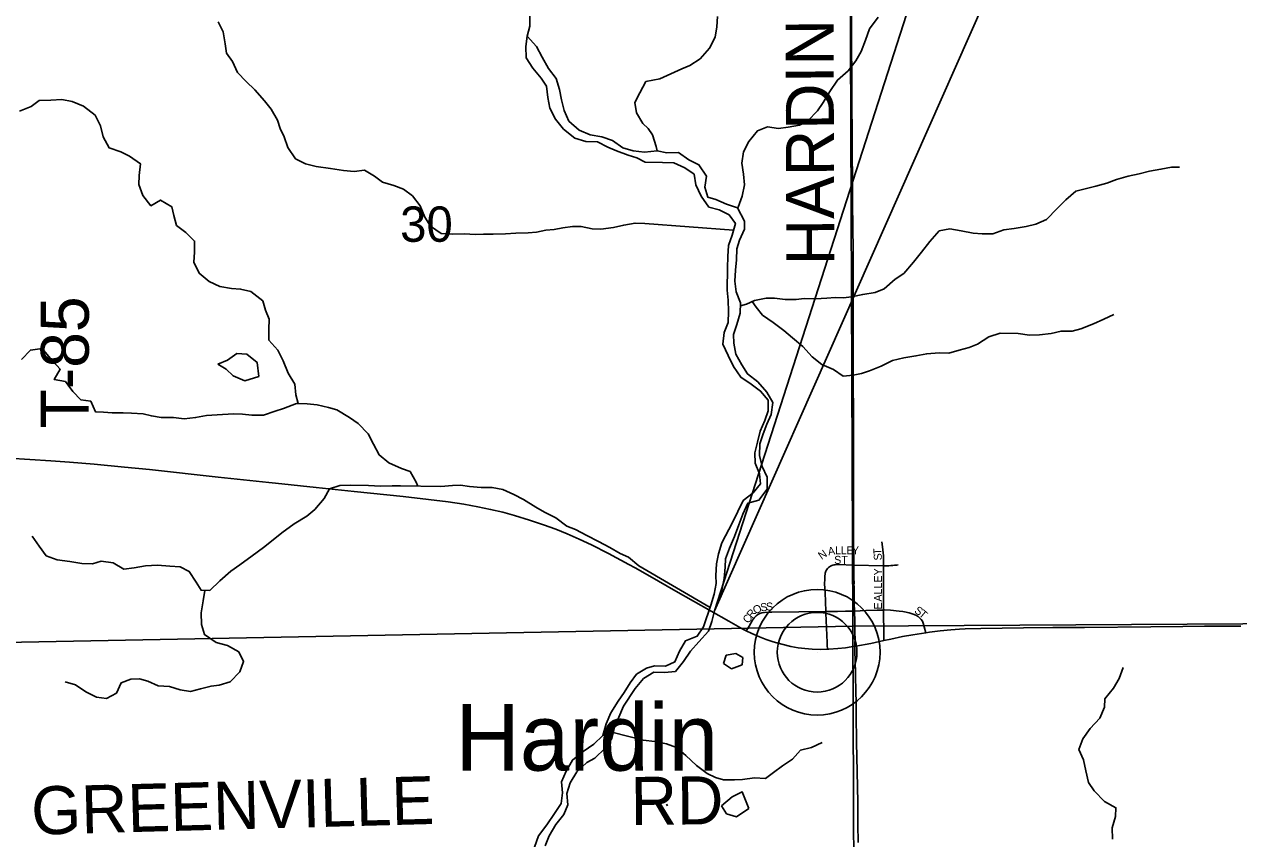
# Model space of a CAD drawing. Extents: x 0 to 1391, y -24 to 440.
# Drawn here: x 387.75 to 416.5, y 344.35 to 363.63 of the extents above; entities that cross this region are included whole.
import ezdxf

# ---------------------------------------------------------------- set-up
doc = ezdxf.new("R2010")
doc.units = 0
for name, color, linetype in [('GM_X_County_Road', 7, 'Continuous'), ('GM_X_County_Road_Text', 7, 'Continuous'), ('GM_X_County_Subdivision', 7, 'Continuous'), ('GM_X_County_Subdivision_Text', 7, 'Continuous'), ('GM_X_Minor_Lake', 7, 'Continuous'), ('GM_X_Minor_River', 7, 'Continuous'), ('GM_X_Section', 7, 'Continuous'), ('GM_X_Section_Text', 7, 'Continuous'), ('GM_X_State_Location', 7, 'Continuous'), ('GM_X_State_Route', 7, 'Continuous'), ('GM_X_Township_Road_Text', 7, 'Continuous'), ('GM_X_Township_Subdivision', 7, 'Continuous'), ('GM_X_Township_Subdivision_Text', 7, 'Continuous'), ('GM_X_Unincorporated', 7, 'Continuous'), ('GM_X_Unincorporated_Location', 7, 'Continuous'), ('GM_X_Unincorporated_Text', 7, 'Continuous'), ('SH_Text', 7, 'Continuous')]:
    doc.layers.add(name, color=color, linetype=linetype)

msp = doc.modelspace()

# ---------------------------------------------------------------- linework, layer by layer
at = {"layer": 'GM_X_County_Road'}
for points in [[(407.387, 350.828), (407.381, 351.521), (407.383, 351.868), (407.385, 352.316), (407.381, 352.813), (407.381, 353.447), (407.383, 353.969), (407.383, 354.13), (407.38, 354.589), (407.377, 354.974), (407.377, 355.571), (407.377, 355.62), (407.374, 355.931), (407.373, 356.142), (407.373, 356.639), (407.373, 356.999), (407.374, 357.31), (407.374, 357.583), (407.374, 358.155), (407.37, 358.478), (407.367, 358.627), (407.363, 358.826), (407.359, 359.398), (407.354, 360.069), (407.35, 360.479), (407.347, 360.863), (407.346, 361.137), (407.344, 361.646), (407.342, 361.845), (407.341, 362.106), (407.34, 362.305), (407.34, 362.541), (407.337, 362.976), (407.334, 363.584), (407.329, 364.317)], [(407.404, 349.739), (407.403, 349.753), (407.399, 349.9), (407.399, 349.987), (407.396, 350.168), (407.395, 350.198), (407.394, 350.235), (407.394, 350.284), (407.394, 350.306), (407.395, 350.307), (407.394, 350.328), (407.393, 350.346), (407.393, 350.356), (407.393, 350.376), (407.394, 350.394), (407.394, 350.416), (407.393, 350.502), (407.389, 350.676), (407.387, 350.828)], [(407.416, 348.905), (407.416, 348.962), (407.418, 349.086), (407.416, 349.211), (407.415, 349.298), (407.413, 349.37), (407.413, 349.395), (407.409, 349.495), (407.404, 349.739)], [(407.49, 344.262), (407.485, 344.689), (407.48, 345.211), (407.469, 345.945), (407.452, 346.628), (407.45, 346.814), (407.444, 347.1), (407.444, 347.634), (407.439, 347.783), (407.428, 348.267), (407.416, 348.814), (407.416, 348.905)]]:
    msp.add_lwpolyline(points, dxfattribs=at)
at = {"layer": 'GM_X_County_Subdivision'}
for points in [[(404.844, 349.273), (404.909, 349.385), (404.99, 349.524), (405.034, 349.584), (405.078, 349.628), (405.118, 349.657), (405.162, 349.68), (405.209, 349.695), (405.271, 349.704), (405.382, 349.71), (405.451, 349.711)], [(405.451, 349.711), (406.727, 349.727)], [(406.727, 349.727), (407.005, 349.731), (407.189, 349.735), (407.312, 349.737), (407.404, 349.739)], [(407.404, 349.739), (407.671, 349.75), (407.943, 349.761), (408.095, 349.764)], [(408.095, 349.764), (408.117, 349.765), (408.254, 349.759), (408.464, 349.74), (408.551, 349.727)], [(408.551, 349.727), (408.587, 349.722), (408.696, 349.697), (408.791, 349.668), (408.859, 349.639), (408.912, 349.607), (408.951, 349.575), (408.984, 349.538), (409.012, 349.497), (409.033, 349.452), (409.056, 349.369), (409.095, 349.227)]]:
    msp.add_lwpolyline(points, dxfattribs=at)
at = {"layer": 'GM_X_Minor_Lake'}
for p, q in [((404.764, 348.638), (404.597, 348.736)), ((404.368, 348.695), (404.303, 348.495)), ((404.303, 348.495), (404.492, 348.374)), ((404.744, 348.467), (404.764, 348.638)), ((404.259, 345.13), (404.378, 344.938))]:
    msp.add_line(p, q, dxfattribs=at)
for points in [[(393.305, 355.294), (393.264, 355.626), (393.017, 355.821), (392.782, 355.833), (392.56, 355.678), (392.332, 355.582)], [(392.332, 355.582), (392.533, 355.466), (392.696, 355.31), (392.975, 355.191), (393.305, 355.294)], [(404.597, 348.736), (404.368, 348.695)], [(404.492, 348.374), (404.744, 348.467)], [(404.904, 345.062), (404.744, 345.461), (404.506, 345.344), (404.259, 345.13)], [(404.378, 344.938), (404.612, 344.865), (404.904, 345.062)]]:
    msp.add_lwpolyline(points, dxfattribs=at)
at = {"layer": 'GM_X_Minor_River'}
for p, q in [((402.445, 358.913), (404.539, 358.757)), ((402.3, 350.812), (403.985, 349.82))]:
    msp.add_line(p, q, dxfattribs=at)
for points in [[(402.445, 358.913), (402.21, 358.925), (401.944, 358.876), (401.701, 358.819), (401.397, 358.779), (401.192, 358.79), (400.935, 358.839), (400.73, 358.843), (400.502, 358.808), (400.297, 358.774), (400.099, 358.754), (399.879, 358.712), (399.681, 358.693), (399.385, 358.683), (399.142, 358.671), (398.854, 358.661), (398.626, 358.657), (398.429, 358.653), (398.164, 358.665), (397.883, 358.662), (397.618, 358.674), (397.37, 358.852), (397.237, 359.067), (397.12, 359.328), (396.942, 359.566), (396.725, 359.729), (396.498, 359.816), (396.234, 359.889), (396.039, 360.037), (395.806, 360.177), (395.563, 360.143), (395.306, 360.17), (395.003, 360.213), (394.663, 360.265), (394.406, 360.322), (394.172, 360.447), (393.987, 360.709), (393.9, 360.968), (393.805, 361.16), (393.747, 361.358), (393.599, 361.619), (393.436, 361.819), (393.205, 362.074), (393.003, 362.275), (392.802, 362.491), (392.677, 362.751), (392.536, 362.944), (392.509, 363.164), (392.46, 363.454), (392.343, 363.684)], [(399.657, 363.35), (399.721, 363.585), (399.717, 363.843)], [(402.468, 362.271), (402.795, 362.338), (403.315, 362.572), (403.506, 362.652), (403.752, 362.815), (403.975, 363.062), (404.108, 363.325), (404.149, 363.567), (404.16, 363.817)], [(404.635, 359.283), (404.651, 359.298), (404.745, 359.562), (404.802, 359.826), (404.775, 360.084), (404.74, 360.343), (404.781, 360.607), (404.906, 360.856), (405.107, 361.11), (405.344, 361.205), (405.602, 361.163), (405.838, 361.197), (406.105, 361.238), (406.297, 361.341), (406.528, 361.58), (406.66, 361.775), (406.823, 362.037), (407.001, 362.307), (407.255, 362.531), (407.44, 362.763), (407.565, 362.988), (407.667, 363.252), (407.761, 363.523), (407.963, 363.801)], [(402.434, 360.6), (402.169, 360.635), (401.92, 360.707), (401.673, 360.878), (401.424, 360.966), (401.151, 361.009), (400.888, 361.119), (400.641, 361.336), (400.531, 361.589), (400.467, 361.84), (400.425, 362.084), (400.346, 362.344), (400.16, 362.582), (400.013, 362.851), (399.873, 363.104), (399.657, 363.35), (399.622, 363.1), (399.633, 362.834), (399.789, 362.588), (399.99, 362.357), (400.116, 362.165), (400.149, 361.899), (400.191, 361.647), (400.323, 361.387), (400.517, 361.148), (400.786, 360.931), (401.043, 360.858), (401.323, 360.846), (401.564, 360.721), (401.767, 360.634), (402.046, 360.53), (402.25, 360.466), (402.45, 360.366)], [(402.521, 361.16), (402.392, 361.284), (402.244, 361.53), (402.203, 361.774), (402.32, 362.007), (402.468, 362.271)], [(394.231, 354.651), (394.182, 354.857), (394.155, 355.108), (394, 355.368), (393.876, 355.659), (393.751, 355.912), (393.543, 356.151), (393.539, 356.401), (393.551, 356.652), (393.463, 356.858), (393.398, 357.08), (393.114, 357.305), (392.872, 357.362), (392.66, 357.373), (392.38, 357.423), (392.131, 357.541), (391.892, 357.735), (391.767, 357.995), (391.778, 358.238), (391.783, 358.497), (391.573, 358.697), (391.356, 358.868), (391.292, 359.105), (391.242, 359.311), (390.979, 359.467), (390.749, 359.334), (390.556, 359.573), (390.461, 359.833), (390.472, 360.053), (390.5, 360.326), (390.245, 360.505), (390.034, 360.607), (389.762, 360.703), (389.622, 360.963), (389.558, 361.223), (389.426, 361.475), (389.156, 361.693), (388.885, 361.803), (388.643, 361.845), (388.377, 361.835), (388.104, 361.824), (387.912, 361.683), (387.637, 361.573)], [(402.732, 360.634), (402.706, 360.74), (402.619, 361.014), (402.521, 361.16)], [(404.344, 350.776), (404.354, 350.973), (404.449, 351.229), (404.567, 351.508), (404.669, 351.779), (404.764, 352.035), (404.881, 352.291), (405.141, 352.362), (405.334, 352.624), (405.338, 352.905), (405.219, 353.164), (405.154, 353.423), (405.165, 353.696), (405.244, 353.937), (405.331, 354.163), (405.433, 354.396), (405.474, 354.676), (405.333, 354.921), (405.116, 355.167), (404.874, 355.353), (404.74, 355.567), (404.599, 355.82), (404.549, 356.078), (404.544, 356.283), (404.616, 356.524), (404.695, 356.788), (404.706, 357.038), (404.603, 357.298), (404.575, 357.548), (404.586, 357.806), (404.612, 358.055), (404.623, 358.313), (404.679, 358.517), (404.804, 358.78), (404.799, 358.97), (404.635, 359.283), (404.378, 359.371), (404.121, 359.481), (403.931, 359.537), (403.858, 359.773), (403.899, 360.03), (403.72, 360.306), (403.486, 360.424), (403.237, 360.595), (402.963, 360.584), (402.736, 360.633), (402.434, 360.6)], [(402.45, 360.366), (402.861, 360.358), (403.127, 360.346), (403.385, 360.228), (403.611, 360.081), (403.646, 359.83), (403.772, 359.563), (403.959, 359.302), (404.201, 359.237), (404.435, 359.12), (404.585, 358.912), (404.505, 358.641), (404.419, 358.392), (404.408, 358.135), (404.397, 357.862), (404.39, 357.339), (404.417, 357.096), (404.422, 356.831), (404.411, 356.573), (404.316, 356.332), (404.29, 356.06), (404.416, 355.785), (404.542, 355.532), (404.714, 355.272), (404.955, 355.109), (405.181, 354.946), (405.361, 354.731), (405.365, 354.481), (405.286, 354.247), (405.169, 353.999), (405.105, 353.735), (405.048, 353.485), (405.053, 353.243), (405.156, 352.991), (405.183, 352.748), (405.006, 352.539), (404.768, 352.353), (404.643, 352.097), (404.518, 351.834), (404.268, 351.353), (404.189, 351.097), (404.14, 350.855), (404.121, 350.583), (404.134, 350.393), (404.085, 350.136), (404.006, 349.88), (403.832, 349.367), (403.684, 349.142), (403.402, 349.033), (403.262, 348.793), (403.152, 348.537), (402.93, 348.435), (402.671, 348.439), (402.481, 348.389), (402.244, 348.245)], [(404.703, 356.964), (404.85, 357.005), (405.041, 357.093), (405.316, 357.149), (405.513, 357.146), (405.764, 357.112), (406.023, 357.115), (406.213, 357.142), (406.479, 357.13), (406.753, 357.149), (406.951, 357.161), (407.141, 357.157), (407.332, 357.177), (407.599, 357.233), (407.896, 357.282), (408.11, 357.369), (408.371, 357.592), (408.571, 357.733), (408.803, 358.002), (408.988, 358.234), (409.189, 358.489), (409.413, 358.743), (409.664, 358.784), (409.93, 358.742), (410.218, 358.684), (410.424, 358.666), (410.682, 358.669), (410.942, 358.763), (411.186, 358.797), (411.468, 358.846), (411.697, 358.895), (411.949, 359.012), (412.203, 359.266), (412.404, 359.475), (412.642, 359.676), (412.894, 359.74), (413.115, 359.797), (413.382, 359.868), (413.604, 359.956), (413.886, 360.034), (414.146, 360.091), (414.39, 360.155), (414.657, 360.196), (414.908, 360.245), (415.099, 360.25)], [(404.983, 357.067), (405.077, 356.934), (405.227, 356.742), (405.476, 356.571), (405.732, 356.377), (405.935, 356.207), (406.183, 355.998), (406.401, 355.76), (406.634, 355.574), (406.907, 355.456), (407.133, 355.301), (407.377, 355.327), (407.567, 355.362), (407.758, 355.427), (408.033, 355.536), (408.301, 355.668), (408.576, 355.732), (408.858, 355.78), (409.117, 355.829), (409.407, 355.855), (409.635, 355.843), (409.879, 355.915), (410.123, 355.979), (410.314, 356.06), (410.583, 356.23), (410.85, 356.316), (411.276, 356.309), (411.549, 356.274), (411.785, 356.278), (412.06, 356.312), (412.296, 356.368), (412.555, 356.364), (412.761, 356.422), (413.066, 356.538), (413.304, 356.648), (413.548, 356.757)], [(397.067, 352.697), (397.031, 352.789), (396.883, 353.042), (396.679, 353.114), (396.378, 353.248), (396.154, 353.434), (396.021, 353.687), (395.889, 353.932), (395.657, 354.179), (395.447, 354.319), (395.154, 354.499), (394.95, 354.555), (394.686, 354.62), (394.444, 354.647), (394.194, 354.651), (393.888, 354.535), (393.69, 354.47), (393.416, 354.375), (393.135, 354.373), (392.915, 354.399), (392.711, 354.41), (392.445, 354.391), (392.065, 354.367), (391.807, 354.318), (391.533, 354.293), (391.283, 354.32), (390.995, 354.324), (390.761, 354.359), (390.564, 354.407), (390.291, 354.42), (390.094, 354.43), (389.829, 354.435), (389.624, 354.446), (389.435, 354.456), (389.325, 354.709), (389.091, 354.743), (388.897, 354.936), (388.726, 355.175), (388.461, 355.217), (388.602, 355.465), (388.363, 355.727), (388.177, 355.951), (387.896, 355.917), (387.688, 355.693)], [(402.3, 350.811), (402.053, 351.013), (401.857, 351.1), (401.609, 351.24), (401.346, 351.389), (401.068, 351.53), (400.797, 351.671), (400.594, 351.751), (400.331, 351.945), (400.068, 352.078), (399.858, 352.196), (399.572, 352.383), (399.339, 352.5), (399.076, 352.619), (398.826, 352.661), (398.568, 352.665), (398.288, 352.685), (398.076, 352.719), (397.886, 352.714), (397.613, 352.688), (396.658, 352.704), (396.46, 352.7), (396.18, 352.697), (395.899, 352.709), (395.467, 352.716), (395.224, 352.713), (394.98, 352.633), (394.848, 352.4), (394.631, 352.145), (394.439, 351.989), (394.14, 351.804), (393.848, 351.589), (393.641, 351.425), (393.418, 351.246), (393.142, 351.046), (392.85, 350.83), (392.643, 350.682), (392.382, 350.458), (392.143, 350.227), (391.938, 350.23), (391.82, 350.422), (391.657, 350.676), (391.439, 350.785), (391.196, 350.805), (390.901, 350.825), (390.62, 350.807), (390.354, 350.765), (390.111, 350.731), (389.855, 350.88), (389.568, 350.923), (389.369, 350.858), (389.112, 350.869), (388.832, 350.912), (388.529, 350.955), (388.273, 351.043), (388.102, 351.273), (387.939, 351.512)], [(402.216, 347.909), (402.409, 348.14), (402.654, 348.295), (402.905, 348.284), (403.164, 348.31), (403.357, 348.542), (403.52, 348.789), (403.721, 349.013), (403.952, 349.267), (404.024, 349.493), (404.088, 349.742), (404.197, 349.998), (404.261, 350.232), (404.318, 350.511), (404.344, 350.776)], [(392.029, 350.229), (391.987, 349.979), (391.937, 349.699), (391.948, 349.425), (392.02, 349.181), (392.29, 348.994), (392.562, 348.922), (392.832, 348.773), (392.942, 348.543), (392.855, 348.302), (392.624, 348.062), (392.364, 347.983), (392.174, 347.963), (391.923, 347.899), (391.687, 347.835), (391.445, 347.877), (391.188, 347.957), (390.923, 347.969), (390.675, 348.079), (390.478, 348.136), (390.273, 348.124), (390.044, 348.037), (389.934, 347.795), (389.697, 347.67), (389.463, 347.705), (389.207, 347.83), (388.967, 347.994), (388.718, 348.066)], [(402.244, 348.245), (402.096, 348.043), (401.956, 347.81), (401.809, 347.607), (401.637, 347.329), (401.527, 347.072), (401.446, 346.793), (401.231, 346.591), (400.985, 346.413), (400.732, 346.212), (400.583, 345.949), (400.465, 345.693), (400.492, 345.434), (400.457, 345.184), (400.302, 344.951), (400.123, 344.681), (399.921, 344.418), (399.826, 344.154)], [(413.509, 344.342), (413.504, 344.607), (413.582, 344.879), (413.592, 345.084), (413.327, 345.231), (413.078, 345.484), (412.942, 345.682), (412.884, 345.956), (412.826, 346.214), (412.714, 346.466), (412.807, 346.715), (412.985, 346.963), (413.215, 347.202), (413.325, 347.466), (413.334, 347.663), (413.534, 347.911), (413.673, 348.144), (413.767, 348.401)], [(400.084, 344.18), (400.179, 344.422), (400.335, 344.685), (400.521, 344.925), (400.616, 345.151), (400.598, 345.417), (400.67, 345.674), (400.833, 345.93), (401.065, 346.154), (401.256, 346.257), (401.502, 346.496), (401.658, 346.721), (401.723, 346.993), (401.825, 347.227), (401.936, 347.491), (402.216, 347.909)], [(401.692, 346.863), (402.405, 346.685), (402.679, 346.651), (402.952, 346.593), (403.194, 346.506), (403.412, 346.32), (403.668, 346.081), (403.916, 345.895), (404.113, 345.801), (404.302, 345.745), (404.561, 345.741), (404.751, 345.753), (405.041, 345.793), (405.299, 345.774), (405.491, 345.915), (405.699, 346.078), (405.937, 346.233), (406.13, 346.45), (406.389, 346.506), (406.641, 346.631)], [(402.975, 345.131), (402.954, 345.172)]]:
    msp.add_lwpolyline(points, dxfattribs=at)
at = {"layer": 'GM_X_Section'}
for points in [[(387.261, 369.12), (407.286, 369.115), (407.364, 349.38), (387.273, 348.998)], [(426.829, 369.053), (427.145, 349.502), (407.364, 349.38), (407.286, 369.115)], [(407.364, 349.38), (407.447, 329.121), (387.293, 328.839), (387.273, 348.998)], [(427.145, 349.502), (427.403, 329.248), (407.447, 329.121), (407.364, 349.38)]]:
    msp.add_lwpolyline(points, close=True, dxfattribs=at)
at = {"layer": 'GM_X_State_Route'}
for points in [[(387.386, 353.357), (388.379, 353.299), (388.825, 353.266), (389.407, 353.213), (390.124, 353.146), (390.718, 353.089), (392.337, 352.912), (393.542, 352.781)], [(393.542, 352.781), (393.695, 352.764), (394.659, 352.662), (395.561, 352.568), (396.724, 352.451), (397.317, 352.383), (397.785, 352.322), (398.154, 352.268), (398.486, 352.21), (398.79, 352.147), (399.081, 352.077), (399.357, 352.002), (399.715, 351.894), (400.045, 351.784), (400.338, 351.678), (400.603, 351.57), (400.888, 351.445), (401.18, 351.306), (401.579, 351.102), (402.062, 350.844), (402.215, 350.759)], [(402.215, 350.759), (402.561, 350.566), (403.176, 350.214), (404.427, 349.497), (404.765, 349.313), (404.844, 349.273), (404.975, 349.208), (405.155, 349.126), (405.316, 349.063), (405.48, 349.009), (405.683, 348.953), (405.9, 348.901), (406.07, 348.87), (406.229, 348.85), (406.401, 348.837), (406.599, 348.833), (406.763, 348.836), (406.797, 348.837), (407.007, 348.85), (407.191, 348.87), (407.416, 348.905), (407.436, 348.908), (407.79, 348.975), (408.099, 349.04), (408.264, 349.074), (408.544, 349.134), (408.788, 349.179), (409.095, 349.227), (409.182, 349.241), (409.429, 349.274), (409.689, 349.296), (409.891, 349.308)], [(409.891, 349.308), (410.025, 349.316), (410.398, 349.327), (411.405, 349.34), (412.1, 349.349), (412.474, 349.349), (412.847, 349.347), (414.421, 349.363), (415.179, 349.375), (415.689, 349.38), (416.099, 349.383), (416.549, 349.381)]]:
    msp.add_lwpolyline(points, dxfattribs=at)
at = {"layer": 'GM_X_Township_Subdivision'}
for points in [[(408.089, 350.808), (408.089, 350.82), (408.091, 350.879), (408.091, 350.95), (408.089, 350.999), (408.088, 351.056), (408.083, 351.121), (408.076, 351.191), (408.067, 351.261), (408.051, 351.379)], [(406.727, 349.727), (406.717, 349.962), (406.707, 350.173), (406.698, 350.385), (406.7, 350.497), (406.703, 350.576), (406.707, 350.609), (406.709, 350.633), (406.717, 350.659), (406.724, 350.682), (406.734, 350.702), (406.75, 350.723), (406.767, 350.743)], [(406.767, 350.743), (406.788, 350.767), (406.812, 350.785), (406.837, 350.805), (406.865, 350.819), (406.894, 350.829), (406.923, 350.834), (406.947, 350.836), (406.976, 350.838), (407.019, 350.839), (407.387, 350.828)], [(407.387, 350.828), (408.089, 350.808)], [(408.089, 350.808), (408.133, 350.808), (408.174, 350.809), (408.221, 350.811), (408.264, 350.814), (408.309, 350.818), (408.352, 350.822), (408.407, 350.828), (408.437, 350.832)], [(408.095, 349.764), (408.089, 350.808)], [(406.763, 348.836), (406.76, 348.932), (406.758, 348.994), (406.729, 349.688), (406.727, 349.727)], [(408.099, 349.04), (408.098, 349.152), (408.095, 349.764)]]:
    msp.add_lwpolyline(points, dxfattribs=at)
at = {"layer": 'GM_X_Unincorporated'}
for radius in [1.488, 0.943]:
    msp.add_circle((406.521, 348.764), radius, dxfattribs=at)
at = {"layer": 'GM_X_Unincorporated_Location'}
msp.add_line((406.521, 348.764), (406.521, 348.764), dxfattribs=at)
at = {"layer": 'SH_Text'}
msp.add_lwpolyline([(404.088, 349.742), (415.194, 384.234), (415.194, 374.799)], close=True, dxfattribs=at)

# ---------------------------------------------------------------- texts
at = {"layer": 'GM_X_County_Road_Text'}
msp.add_text('HARDIN', height=1.1364, rotation=90.176, dxfattribs=at).set_placement((406.927, 357.925))
at = {"layer": 'GM_X_County_Subdivision_Text'}
for s, rotation, p in [('O', 26.7996, (405.056, 349.657)), ('S', 8.9144, (405.19, 349.727)), ('S', 3.1162, (405.316, 349.747)), ('C', 54.7474, (404.894, 349.432)), ('R', 51.5564, (404.979, 349.553)), ('S', 327.204, (408.807, 349.711)), ('T', 319.6032, (408.914, 349.642))]:
    msp.add_text(s, height=0.189, rotation=rotation, dxfattribs=at).set_placement(p)
at = {"layer": 'GM_X_Section_Text'}
msp.add_text('30', height=0.8371, rotation=0, dxfattribs=at).set_placement((396.649, 358.48))
at = {"layer": 'GM_X_State_Location'}
for s in ['s', 'r']:
    msp.add_text(s, height=0.00379, dxfattribs=at).set_placement((402.244, 351.177))
msp.add_text('47', height=0.00379, rotation=0, dxfattribs=at).set_placement((401.29, 350.902))
at = {"layer": 'GM_X_Township_Road_Text'}
for s, rotation, p in [('T-85', 90, (389.279, 354.063)), ('GREENVILLE', 1.5448, (387.93, 344.443)), ('RD', 0.4852, (402.11, 344.676))]:
    msp.add_text(s, height=1.1364, rotation=rotation, dxfattribs=at).set_placement(p)
at = {"layer": 'GM_X_Township_Subdivision_Text'}
for s, height, rotation, p in [('N', 0.189, 35.0601, (406.627, 350.947)), ('A', 0.189, 9.3761, (406.789, 351.054)), ('ST', 0.1894, 0, (406.924, 350.856)), ('L', 0.189, 0.4098, (406.946, 351.081)), ('L', 0.189, 0, (407.078, 351.082)), ('E', 0.189, 0, (407.212, 351.082)), ('Y', 0.189, 0, (407.345, 351.082)), ('T', 0.189, 93.0889, (408.046, 351.076)), ('S', 0.189, 93.636, (408.055, 350.943)), ('ALLEY', 0.1894, 90, (408.055, 349.963)), ('E', 0.189, 90, (408.055, 349.779))]:
    msp.add_text(s, height=height, rotation=rotation, dxfattribs=at).set_placement(p)
at = {"layer": 'GM_X_Unincorporated_Text'}
msp.add_text('Hardin', height=1.5795, rotation=0, dxfattribs=at).set_placement((397.957, 345.962))

doc.saveas('drawing.dxf')
